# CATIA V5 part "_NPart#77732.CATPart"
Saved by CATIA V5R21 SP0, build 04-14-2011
Part number: Chapa Intermediária
Definition: Chapa Intermediária
Nomenclature: Chapa Intermediária
Source: Unknown
Bounding box of the stored display mesh (mm): x -6 to 6, y -2.8 to 0.8, z -5 to 5
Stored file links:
  C:\Users\beatr\OneDrive\Documents\UNB\2026_1\Pi1\Componentes eletronicos\_NPart#77732.CATPart
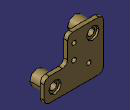
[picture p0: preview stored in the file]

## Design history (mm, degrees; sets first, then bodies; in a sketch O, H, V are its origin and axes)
Body1 "Sólido1" (main body)
  Solid1: solid without history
